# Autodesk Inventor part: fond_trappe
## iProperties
Created: 2011-01
Part Number: fond_trappe
Document SubType Name: Modeling
Designer: eric
Density: 1 g/cm^3
Mass: 5.36742 g
Surface Area: 110.446 cm^2
Volume: 5.36742 cm^3
Author: eric
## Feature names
1. Base1
